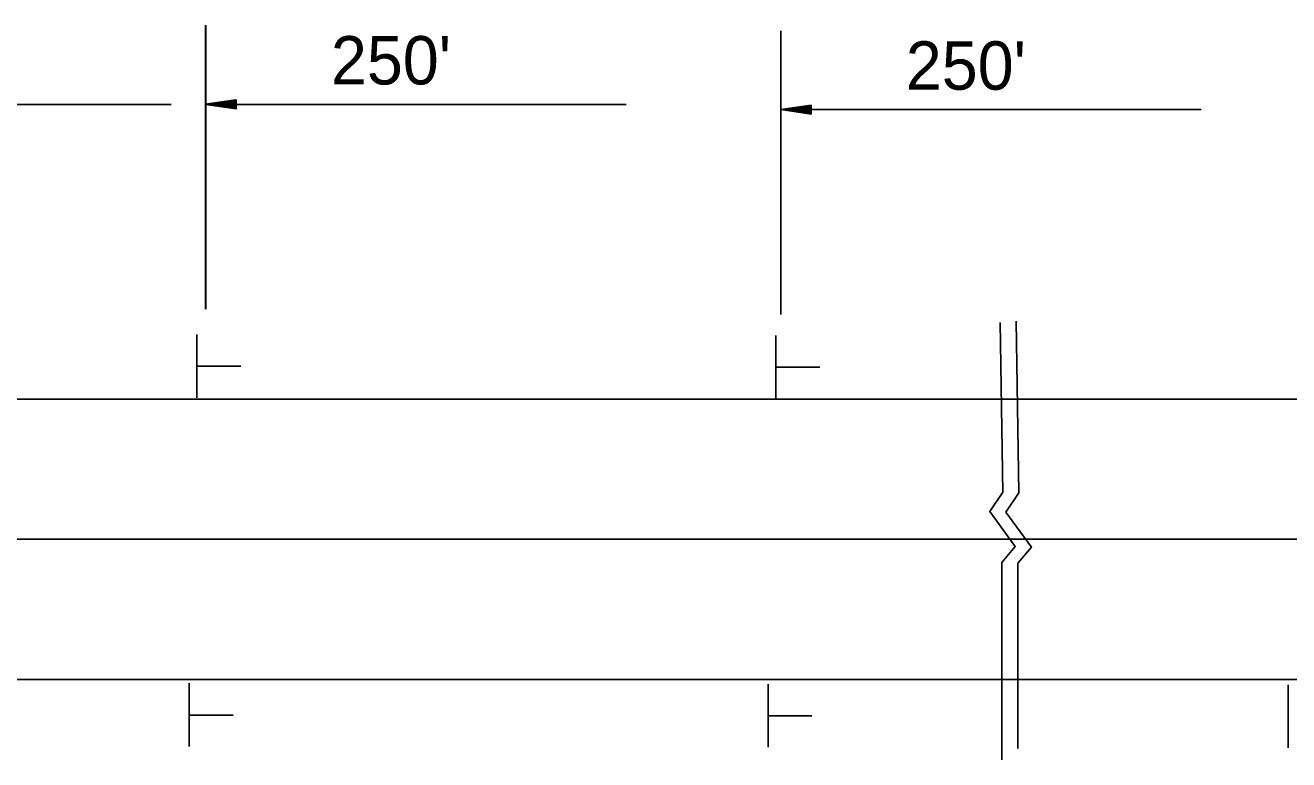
# Model space of a CAD drawing. Extents: x 1398460 to 1408037, y 380768 to 383968.
# Drawn here: x 1399197.2 to 1399354.1, y 382524.2 to 382615.3 of the extents above; entities that cross this region are included whole.
import ezdxf

# ---------------------------------------------------------------- set-up
doc = ezdxf.new("R2010")
doc.units = 0
doc.layers.add('Default', color=7, linetype='Continuous')

msp = doc.modelspace()

# ---------------------------------------------------------------- linework, layer by layer
at = {"layer": 'Default'}
for p, q in [((1399219.59, 382615.27), (1399219.59, 382580.06)), ((1399219.63, 382615.25), (1399219.63, 382580.04)), ((1399291.02, 382614.6), (1399291.02, 382579.39)), ((1399163.13, 382605.46), (1399215.32, 382605.46)), ((1399223.34, 382606.04), (1399219.59, 382605.48)), ((1399223.34, 382604.92), (1399219.59, 382605.48)), ((1399223.38, 382606.02), (1399219.63, 382605.46)), ((1399223.38, 382604.9), (1399219.63, 382605.46)), ((1399219.63, 382605.46), (1399271.82, 382605.46)), ((1399223.34, 382605.95), (1399220.22, 382605.48)), ((1399223.34, 382605.01), (1399220.22, 382605.48)), ((1399223.38, 382605.93), (1399220.26, 382605.46)), ((1399223.38, 382604.99), (1399220.26, 382605.46)), ((1399223.34, 382605.85), (1399220.87, 382605.48)), ((1399223.34, 382605.11), (1399220.87, 382605.48)), ((1399223.38, 382605.83), (1399220.9, 382605.46)), ((1399223.38, 382605.09), (1399220.9, 382605.46)), ((1399223.34, 382605.76), (1399221.49, 382605.48)), ((1399223.34, 382605.2), (1399221.49, 382605.48)), ((1399223.38, 382605.74), (1399221.53, 382605.46)), ((1399223.38, 382605.18), (1399221.53, 382605.46)), ((1399223.34, 382605.66), (1399222.13, 382605.48)), ((1399223.34, 382605.3), (1399222.13, 382605.48)), ((1399223.38, 382605.64), (1399222.16, 382605.46)), ((1399223.38, 382605.28), (1399222.16, 382605.46)), ((1399223.34, 382605.57), (1399222.75, 382605.48)), ((1399223.34, 382605.39), (1399222.75, 382605.48)), ((1399223.38, 382605.55), (1399222.79, 382605.46)), ((1399223.38, 382605.37), (1399222.79, 382605.46)), ((1399223.34, 382604.92), (1399223.34, 382606.04)), ((1399223.38, 382604.9), (1399223.38, 382606.02)), ((1399294.77, 382605.38), (1399291.02, 382604.81)), ((1399291.02, 382604.81), (1399343.21, 382604.81)), ((1399294.77, 382604.25), (1399291.02, 382604.81)), ((1399294.77, 382605.28), (1399291.64, 382604.81)), ((1399294.77, 382604.34), (1399291.64, 382604.81)), ((1399294.77, 382605.19), (1399292.29, 382604.81)), ((1399294.77, 382604.44), (1399292.29, 382604.81)), ((1399294.77, 382605.09), (1399292.91, 382604.81)), ((1399294.77, 382604.53), (1399292.91, 382604.81)), ((1399294.77, 382605), (1399293.55, 382604.81)), ((1399294.77, 382604.63), (1399293.55, 382604.81)), ((1399294.77, 382604.9), (1399294.17, 382604.81)), ((1399294.77, 382604.73), (1399294.17, 382604.81)), ((1399294.77, 382604.25), (1399294.77, 382605.38)), ((1399218.52, 382569.07), (1399218.52, 382576.9)), ((1399290.4, 382568.96), (1399290.4, 382576.78)), ((1399218.64, 382572.96), (1399223.98, 382572.96)), ((1399290.51, 382572.85), (1399295.85, 382572.85)), ((1399143.58, 382568.89), (1399212.35, 382568.89)), ((1399212.35, 382568.89), (1399246.6, 382568.89)), ((1399246.6, 382568.89), (1399313.22, 382568.89)), ((1399313.22, 382568.89), (1399382.23, 382568.89)), ((1399143.58, 382551.51), (1399213.12, 382551.51)), ((1399213.12, 382551.51), (1399252.05, 382551.51)), ((1399252.05, 382551.51), (1399313.22, 382551.51)), ((1399313.22, 382551.51), (1399382.23, 382551.51)), ((1399143.58, 382534.12), (1399212.41, 382534.12)), ((1399212.41, 382534.12), (1399246.66, 382534.12)), ((1399246.66, 382534.12), (1399313.22, 382534.12)), ((1399313.22, 382534.12), (1399382.23, 382534.12)), ((1399217.56, 382525.81), (1399217.56, 382533.64)), ((1399289.43, 382525.7), (1399289.43, 382533.52)), ((1399354.03, 382525.64), (1399354.03, 382533.46)), ((1399217.67, 382529.7), (1399223.01, 382529.7)), ((1399289.55, 382529.59), (1399294.89, 382529.59))]:
    msp.add_line(p, q, dxfattribs=at)
for points in [[(1399318.27, 382578.39), (1399318.59, 382557.36), (1399316.97, 382554.94), (1399320.13, 382550.61), (1399318.47, 382548.61), (1399318.46, 382524.16)], [(1399320.26, 382578.58), (1399320.59, 382557.27), (1399318.96, 382554.86), (1399322.13, 382550.53), (1399320.46, 382548.53), (1399320.46, 382525.56)]]:
    msp.add_lwpolyline(points, dxfattribs=at)

# ---------------------------------------------------------------- texts
for p in [(1399235.16, 382607.93), (1399306.54, 382607.28)]:
    msp.add_text("250'", height=6, dxfattribs=at).set_placement(p)

doc.saveas('drawing.dxf')
